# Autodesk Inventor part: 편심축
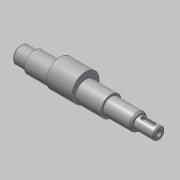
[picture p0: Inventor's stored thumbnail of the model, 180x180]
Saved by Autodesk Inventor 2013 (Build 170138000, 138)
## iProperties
Created: 2019-05
Part Number: 편심축
Material: 강철, 연강
Document SubType Name: Modeling
Designer: mduedu
Density: 7.86 g/cm^3
Mass: 359.395 g
Surface Area: 100.517 cm^2
Volume: 45.7245 cm^3
Author: mduedu
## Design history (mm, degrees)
sketch "스케치1"
  geometry: L1 (0, 0)-(14, 0); L2 (14, 0)-(14, 8.5); L3 (14, 8.5)-(0, 8.5); L4 (0, 8.5)-(0, 0); L5 (14, 0)-(92, 0); L6 (92, 0)-(92, 10.5); L7 (92, 10.5)-(14, 10.5); L8 (14, 10.5)-(14, 0); L9 (92, 8.5)-(92, 0); L10 (92, 0)-(121, 0); L11 (121, 0)-(121, 8.5); L12 (121, 8.5)-(92, 8.5); L13 (92, 8.5)-(92, 0); L14 (121, 0)-(141, 0); L15 (141, 0)-(141, 6); L16 (141, 6)-(121, 6); L17 (121, 6)-(121, 0)
  constraints: 34 end point, 8 parallel, 4 horizontal, 4 perpendicular
  dimensions: "d2" = 14 distance of L2.end L3.end; "d5" = 17 diameter of L3 L1; "d6" = 21 diameter of L7 L5; "d11" = 78 distance of L6.end L7.end (derived); "d12" = 141 distance between parallel lines of L15 L4; "d13" = 20 distance of L15.end L16.end; "d14" = 49 distance between parallel lines of L15 L6; "d15" = 12 diameter of L16 L14; "d16" = 17 diameter of L12 L10
revolve "회전1" sketch "스케치1" stored, may be unused: angle "d17" = 90 deg
node "작업 평면1"
sketch "스케치2"
  geometry: C1 r 14 at (0, 3.5); C2 r 10.5 at (0, 0) reference; 1 further point
  constraints: 1 centre point, 1 tangent, 1 vertical alignment
  dimensions: "d18" = 28 diameter of C1; "d21" = 3.5 distance of C1.centre point (0, 0) (derived)
extrude "돌출1" join sketch "스케치2" stored distance "d19" = 26; taper "d20" = 0 deg
hole "구멍2" diameter "d45" = 3.242; stored, may be unused: countersink angle "d49" = 60 deg, drill point angle "d51" = 118 deg; dims "d43" = 10, "d44" = 10, "d46" = 8, "d47" = 6.7, "d48" = 2, "d50" = 10
chamfer "모따기3" distance "d52" = 2; stored, may be unused: second distance "d53" = 2, angle "d54" = 30 deg
node "작업 평면2"
sketch "스케치3" dims "d32" = 14
  geometry: L1 (6, -2)-(-4, -2); L2 (-4, -2)-(-4, 2); L3 (-4, 2)-(6, 2); L4 (6, 2)-(6, -2); L5 (10, 8.5)-(10, -8.5) reference; 3 further points
  constraints: 8 end point, 2 midpoint, 2 parallel, 2 vertical alignment, 1 horizontal, 1 horizontal alignment, 1 perpendicular, 4 other
  dimensions: "d31" = 2 dimension on L5; "d33" = 4 distance between parallel lines of L3 L1
extrude "돌출2" cut sketch "스케치3" distance "d34" = 2.5; taper "d35" = 0 deg
chamfer "모따기1" distance "d36" = 1; stored, may be unused: second distance "d37" = 2, angle "d38" = 45 deg
fillet "모깎기1" dims "d39" = 0.3
chamfer "모따기2" distance "d40" = 1.82; stored, may be unused: second distance "d41" = 2, angle "d42" = 30 deg
fillet "모깎기2" dims "d55" = 2
fillet "모깎기3" dims "d56" = 0.5
node "솔리드1"
